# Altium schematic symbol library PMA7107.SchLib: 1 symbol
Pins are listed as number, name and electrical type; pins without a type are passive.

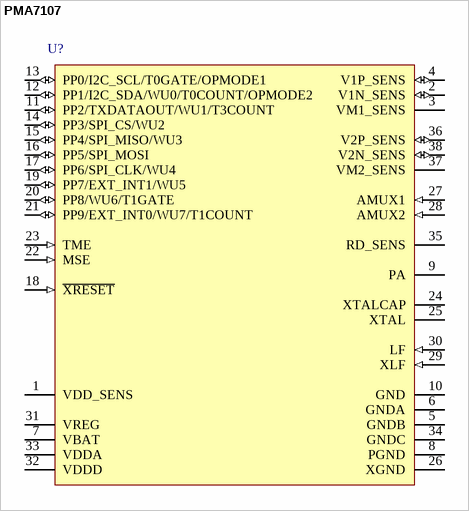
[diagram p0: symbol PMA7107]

## PMA7107
designator U?
RF Transmitter ASK / FSK 315 / 434 / 868 / 915 MHz, Embedded 8051 Microcontroller, 10-bit ADC, 125 kHz ASK LF Receiver, -40 to 85 degC, PG-TSSOP-38, Green; Manufacturer: Infineon; PartNumber: PMA7107; Channel Requirements per Band: Single Channel; Frequency Band: 315 MHz, 434 MHz, 868 MHz, 915 MHz; Green: yes; Transmit Power (at 3V): 5 dBm, 8 dBm, 10 dBm
footprint INF-PG-TSSOP-38_N (SOP, 38-Leads, Body 9.7x4.4 mm, Pitch 0.5 mm, IPC Medium Density)
footprint INF-PG-TSSOP-38_L (SOP, 38-Leads, Body 9.7x4.4 mm, Pitch 0.5 mm, IPC High Density)
footprint INF-PG-TSSOP-38_M (SOP, 38-Leads, Body 9.7x4.4 mm, Pitch 0.5 mm, IPC Low Density)
pins: 1 VDD_SENS (power) "Sensor Bridge Positive Supply Output of VReg  during  measurement.", 2 V1N_SENS (io) "Channel 6, High-gain ADC Input Negative input connect to sensor  bridge. Output of wheatstone bridge sensor", 3 VM1_SENS (power) "Channel 6, High-gain ADC Input Sensor bridge negative supply. Same voltage as chip GND.", 4 V1P_SENS (io) "Channel 6, High-gain ADC Input Positive input connect to sensor  bridge. Output of wheatstone bridge sensor", 5 GNDB (power) "Ground", 6 GNDA (power) "Ground", 7 VBAT (power) "Battery Supply Voltage  Regulators", 8 PGND (power) "Power Amplifier Ground Double bond", 9 PA (oc) "Power Amplifier Output Stage", 10 GND (power) "Ground", 11 PP2/TXDATAOUT/WU1/T3COUNT (io) "PP2 -) Serial output of Manchester /  Biphase encoded data. -) GPIO -) External wake-up source 1 -) Clock source for Timer 3 -) Internal, switchable pull-up/pull-down.", 12 PP1/I2C_SDA/WU0/T0COUNT/OPMODE2 (io) "PP1 -) I2C bus interface data -) GPIO -) External wake-up source 0 -) Clock source for Timer 0 -) Select operation mode -) Internal, switchable pull-up/pull-down.", 13 PP0/I2C_SCL/T0GATE/OPMODE1 (io) "PP0 -) I2C bus interface clock -) GPIO -) External enable for Timer 0 -) Select operation mode -) Internal, switchable pull-up/pull-down.", 14 PP3/SPI_CS/WU2 (io) "PP3 -) SPI bus interface chip select -) GPIO -) External wake-up source 2 -) Internal, switchable pull-up/pull-down.", 15 PP4/SPI_MISO/WU3 (io) "PP4 -) SPI bus interface master in slave  out -) GPIO -) External wake-up source 3 -) Internal, switchable pull-up/pull-down.", 16 PP5/SPI_MOSI (io) "PP5 -) SPI bus interface master out  slave in -) GPIO -) Internal, switchable pull-up/pull-down.", 17 PP6/SPI_CLK/WU4 (io) "PP6 -) SPI bus interface clock -) GPIO -) External wake-up source 4 -) Internal, switchable pull-up/pull-down.", 18 ~{XRESET} (in) "External Reset Low active", 19 PP7/EXT_INT1/WU5 (io) "PP7 -) GPIO -) External interrupt source 1 -) External wake-up source 5 -) Internal, switchable pull-up/pull-down.", 20 PP8/WU6/T1GATE (io) "PP8 -) GPIO -) External wake-up source 6 -) External enable for Timer 1 -) Internal, switchable pull-up/pull-down.", 21 PP9/EXT_INT0/WU7/T1COUNT (io) "PP9 -) GPIO -) External interrupt source 0 -) External wake-up source 7 -) Clock source for Timer 1 -) Internal, switchable pull-up/pull-down.", 22 MSE (in) "Mode Select Enable High active, set to GND in NORMAL Mode.", 23 TME (in) "Test Mode Enable, n.a. for  Normal Application Has to be set to GND in NORMAL Mode", 24 XTALCAP "Crystal Oscillator Load  Capacitance", 25 XTAL "Crystal Oscillator Input", 26 XGND (power) "Crystal Oscillator Ground", 27 AMUX1 (in) "Additional Differential ADC  Standard Input1 for External  Sensor Connect to GND if not use.", 28 AMUX2 (in) "Additional Differential ADC  Standard Input2 for External  Sensor Connect to GND if not use.", 29 XLF (in) "Differential LF Receiver Input2 125kHz Input.", 30 LF (in) "Differential LF Receiver Input1", 31 VREG (power) "Internal Voltage Regulator  Output Connect to decoupling capacitor  (CBCAP =100 nF) Regulated Power supply.", 32 VDDD (power) "Digital Supply", 33 VDDA (power) "Analog Supply", 34 GNDC (power) "Ground", 35 RD_SENS "Diagnostic Resistor Use only by having diagnostic  resistor on sensor bridge for highgain ADC input, otherwise no  connection", 36 V2P_SENS (io) "Channel 7, High-gain ADC Input Positive input connect to sensor  bridge. Output of Wheatstone bridge  sensor.", 37 VM2_SENS (power) "Channel 7, High-gain ADC Input Sensor bridge negative supply. Same voltage as chip GND.", 38 V2N_SENS (io) "Channel 7, High-gain ADC Input Negative input connect to sensor  bridge. Output of Wheatstone bridge  sensor."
